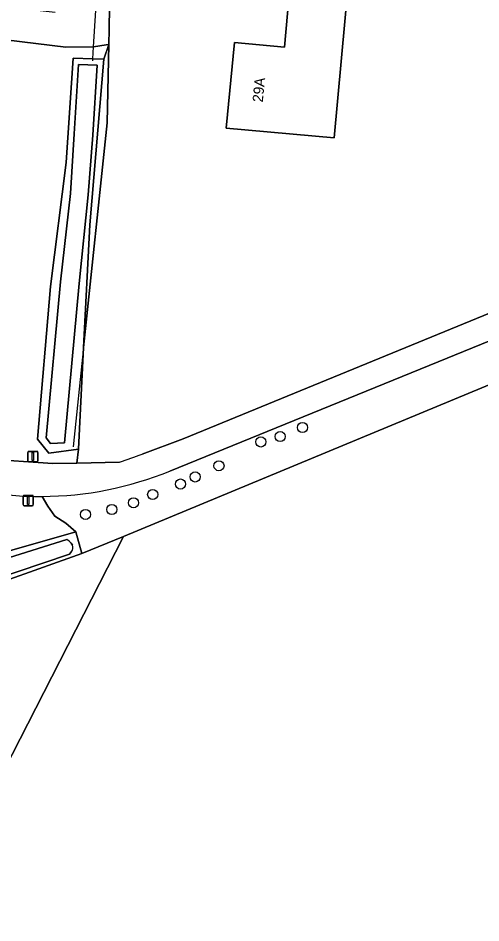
# Model space of a CAD drawing. Extents: x 162510 to 163918, y 388494 to 389774.
# Drawn here: x 162663.6 to 162708.2, y 389474.6 to 389562 of the extents above; entities that cross this region are included whole.
import ezdxf

# ---------------------------------------------------------------- set-up
doc = ezdxf.new("R2010")
doc.units = 0
for name, color, linetype in [('IMGEO_Afsluitpaal', 7, 'Continuous'), ('IMGEO_Boom', 7, 'Continuous'), ('IMGEO_Duiker', 7, 'Continuous'), ('IMGEO_Erf', 7, 'Continuous'), ('IMGEO_Grasland_agrarisch', 7, 'Continuous'), ('IMGEO_Grasland_overig', 7, 'Continuous'), ('IMGEO_Groenvoorziening', 7, 'Continuous'), ('IMGEO_Hek', 7, 'Continuous'), ('IMGEO_Loofbos', 7, 'Continuous'), ('IMGEO_Oever', 7, 'Continuous'), ('IMGEO_Pand', 7, 'Continuous'), ('IMGEO_Pand_nummerreeks', 7, 'Continuous'), ('IMGEO_Rijbaan_lokaal_onverhard', 7, 'Continuous'), ('IMGEO_Rijbaan_lokaal_open', 7, 'Continuous'), ('IMGEO_Waterloop', 7, 'Continuous')]:
    doc.layers.add(name, color=color, linetype=linetype)

msp = doc.modelspace()

# ---------------------------------------------------------------- linework, layer by layer
at = {"layer": 'IMGEO_Afsluitpaal'}
for p, q in [((162664.499, 389519.217), (162664.499, 389520.017)), ((162664.499, 389520.017), (162664.499, 389519.217)), ((162664.599, 389520.117), (162665.389, 389520.117)), ((162665.389, 389520.117), (162664.599, 389520.117)), ((162665.489, 389520.017), (162665.489, 389519.217)), ((162665.489, 389519.217), (162665.489, 389520.017)), ((162665.389, 389519.117), (162664.599, 389519.117)), ((162664.599, 389519.117), (162665.389, 389519.117)), ((162664.047, 389514.97), (162664.047, 389515.77)), ((162664.047, 389515.77), (162664.047, 389514.97)), ((162664.147, 389515.87), (162664.937, 389515.87)), ((162664.937, 389515.87), (162664.147, 389515.87)), ((162665.037, 389515.77), (162665.037, 389514.97)), ((162665.037, 389514.97), (162665.037, 389515.77)), ((162664.937, 389514.87), (162664.147, 389514.87)), ((162664.147, 389514.87), (162664.937, 389514.87))]:
    msp.add_line(p, q, dxfattribs=at)
for points in [[(162664.919, 389519.992), (162665.069, 389519.992), (162665.069, 389519.242), (162664.919, 389519.242), (162664.919, 389519.992)], [(162664.467, 389515.745), (162664.617, 389515.745), (162664.617, 389514.995), (162664.467, 389514.995), (162664.467, 389515.745)]]:
    msp.add_lwpolyline(points, dxfattribs=at)
for centre, start, end in [((162664.599, 389520.017), 90, 180), ((162664.599, 389520.017), 90, 180), ((162665.389, 389520.017), 0, 90), ((162665.389, 389520.017), 360, 90), ((162664.599, 389519.217), 180, 270), ((162664.599, 389519.217), 180, 270), ((162665.389, 389519.217), 270, 0), ((162665.389, 389519.217), 270, 0), ((162664.147, 389515.77), 90, 180), ((162664.147, 389515.77), 90, 180), ((162664.937, 389515.77), 0, 90), ((162664.937, 389515.77), 360, 90), ((162664.147, 389514.97), 180, 270), ((162664.147, 389514.97), 180, 270), ((162664.937, 389514.97), 270, 0), ((162664.937, 389514.97), 270, 0)]:
    msp.add_arc(centre, 0.1, start, end, dxfattribs=at)
at = {"layer": 'IMGEO_Boom'}
for centre in [(162691.022, 389522.421), (162688.864, 389521.544), (162686.995, 389521.025), (162682.955, 389518.729), (162680.661, 389517.646), (162679.239, 389516.963), (162676.559, 389515.948), (162674.703, 389515.155), (162672.623, 389514.495), (162670.069, 389514.029)]:
    msp.add_circle(centre, 0.489, dxfattribs=at)
at = {"layer": 'IMGEO_Duiker'}
msp.add_lwpolyline([(162670.773, 389557.836), (162670.785, 389558.031), (162670.855, 389559.19), (162671.066, 389562.679), (162671.154, 389564.123), (162671.18, 389564.555)], dxfattribs=at)
at = {"layer": 'IMGEO_Erf'}
for points in [[(162705.553, 389603.519), (162699.993, 389600.99), (162689.359, 389596.706), (162682.449, 389594.589), (162674.426, 389591.992), (162672.343, 389591.571), (162672.542, 389590.328), (162672.733, 389578.637), (162672.968, 389564.254), (162672.43, 389564.215), (162672.405, 389563.043), (162672.36, 389560.903), (162672.329, 389559.407), (162672.17, 389551.859), (162669.89, 389530.138), (162669.389, 389520.319), (162669.237, 389518.99), (162673.37, 389519.086)], [(162675.536, 389519.846), (162679.516, 389521.342), (162765.327, 389556.557), (162788.119, 389565.57), (162797.51, 389568.666), (162797.54, 389568.676)]]:
    msp.add_lwpolyline(points, dxfattribs=at)
msp.add_lwpolyline([(162694.093, 389550.388), (162683.643, 389551.344), (162684.466, 389559.606), (162689.277, 389559.141), (162689.907, 389566.028), (162695.476, 389565.519)], close=True, dxfattribs=at)
msp.add_arc((162664.749, 389547.121), 29.331, 287.09222, 291.5774, dxfattribs=at)
at = {"layer": 'IMGEO_Grasland_agrarisch'}
msp.add_lwpolyline([(162827.332, 389516.707), (162785.51, 389500), (162768.198, 389493.084), (162765.022, 389491.815), (162747.635, 389542.568), (162673.743, 389511.906), (162660.641, 389486.295), (162645.792, 389460.138), (162630.336, 389430.938), (162620.125, 389411.441), (162611.16, 389387.648), (162603.73, 389364.734), (162600.094, 389349.342), (162595.223, 389323.119), (162589.654, 389295.27), (162587.18, 389279.327)], dxfattribs=at)
at = {"layer": 'IMGEO_Grasland_overig'}
msp.add_lwpolyline([(162671.835, 389558.007), (162670.495, 389542.008), (162669.89, 389530.138), (162672.17, 389551.859), (162672.329, 389559.407)], close=True, dxfattribs=at)
msp.add_lwpolyline([(162620.125, 389411.441), (162630.336, 389430.938), (162645.792, 389460.138), (162660.641, 389486.295), (162673.743, 389511.906), (162669.724, 389510.239), (162658.13, 389506.139), (162654.637, 389500), (162643.958, 389481.233), (162638.44, 389471.713), (162635.685, 389466.725), (162634.256, 389464.148), (162613.419, 389423.521), (162610.195, 389417.846), (162606.388, 389409.531), (162602.54, 389399.816), (162600.275, 389394.519)], dxfattribs=at)
at = {"layer": 'IMGEO_Groenvoorziening'}
msp.add_lwpolyline([(162668.207, 389548.027), (162668.877, 389558.074), (162670.785, 389558.031), (162671.835, 389558.007), (162672.329, 389559.407), (162672.082, 389559.371), (162670.855, 389559.19), (162668.162, 389559.157), (162662.376, 389559.853), (162661.677, 389555.433), (162659.449, 389542.704), (162657.818, 389535.123), (162655.773, 389526.565), (162654.035, 389520.655), (162659.439, 389519.57), (162660.287, 389519.4), (162666.922, 389518.936), (162669.237, 389518.99), (162669.389, 389520.319), (162666.547, 389519.929), (162665.429, 389521.303), (162666.698, 389536.028)], close=True, dxfattribs=at)
msp.add_lwpolyline([(162659.366, 389513.063), (162659.445, 389512.758), (162659.494, 389512.434), (162659.314, 389509.549), (162669.129, 389512.345), (162668.181, 389513.167), (162667.108, 389513.867), (162666.432, 389514.835), (162665.882, 389515.761)], dxfattribs=at)
msp.add_arc((162665.71, 389549.239), 33.478, 260.35279, 270.29381, dxfattribs=at)
at = {"layer": 'IMGEO_Hek'}
for points in [[(162672.36, 389560.903), (162672.405, 389563.043)], [(162672.36, 389560.903), (162672.329, 389559.407)], [(162672.329, 389559.407), (162672.17, 389551.859), (162669.89, 389530.138)], [(162669.89, 389530.138), (162668.882, 389520.541)]]:
    msp.add_lwpolyline(points, dxfattribs=at)
at = {"layer": 'IMGEO_Loofbos'}
for points in [[(162750.859, 389543.906), (162749.683, 389547.352), (162678.223, 389518.21)], [(162665.882, 389515.761), (162666.432, 389514.835), (162667.108, 389513.867), (162668.181, 389513.167), (162669.129, 389512.345), (162669.724, 389510.239), (162673.743, 389511.906), (162747.635, 389542.568), (162750.859, 389543.906)]]:
    msp.add_lwpolyline(points, dxfattribs=at)
msp.add_arc((162665.691, 389549.044), 33.283, 270.32919, 292.1192, dxfattribs=at)
at = {"layer": 'IMGEO_Oever'}
for points in [[(162670.495, 389542.008), (162671.835, 389558.007), (162670.785, 389558.031), (162668.877, 389558.074), (162668.207, 389548.027), (162666.698, 389536.028), (162665.429, 389521.303), (162666.547, 389519.929), (162669.389, 389520.319), (162669.89, 389530.138)], [(162669.388, 389557.49), (162671.197, 389557.429), (162670.797, 389550.668), (162670.346, 389544.879), (162669.466, 389536.319), (162668.061, 389520.93), (162666.696, 389520.865), (162666.293, 389521.425), (162667.666, 389536.503), (162668.627, 389545.028), (162668.991, 389550.778)]]:
    msp.add_lwpolyline(points, close=True, dxfattribs=at)
for points in [[(162634.256, 389464.148), (162635.685, 389466.725), (162638.44, 389471.713), (162643.958, 389481.233), (162654.637, 389500), (162658.13, 389506.139), (162669.724, 389510.239), (162669.129, 389512.345), (162659.314, 389509.549), (162659.494, 389512.434), (162659.445, 389512.758), (162659.366, 389513.063)], [(162636.578, 389471.099), (162639.037, 389475.684), (162641.975, 389481.475), (162643.39, 389484.648), (162649.254, 389497.836), (162653.92, 389506.356), (162657.551, 389513.059), (162658.86, 389512.638), (162658.709, 389508.6), (162668.26, 389511.601)], [(162668.704, 389511.263), (162668.826, 389511.049)], [(162668.737, 389510.454), (162668.635, 389510.321), (162668.523, 389510.19), (162658.39, 389506.787), (162657.559, 389506.341), (162643.33, 389480.856), (162640.007, 389475.184), (162633.793, 389463.772), (162631.706, 389459.707), (162629.667, 389455.808), (162626.032, 389448.621), (162622.316, 389441.292), (162613.522, 389424.144), (162610.047, 389417.95), (162607.536, 389412.566), (162604.252, 389404.959), (162602.241, 389399.806), (162600.325, 389394.951), (162599.784, 389393.765), (162599.088, 389391.643), (162596.849, 389385.147), (162595.479, 389380.912), (162593.289, 389373.253), (162591.117, 389365.304)]]:
    msp.add_lwpolyline(points, dxfattribs=at)
for centre, radius, start, end in [((162667.625, 389510.306), 1.442, 41.56592, 63.87285), ((162668.281, 389510.826), 0.589, 320.78844, 22.19712)]:
    msp.add_arc(centre, radius, start, end, dxfattribs=at)
at = {"layer": 'IMGEO_Pand'}
msp.add_lwpolyline([(162689.277, 389559.141), (162684.466, 389559.606), (162683.643, 389551.344), (162694.093, 389550.388), (162695.476, 389565.519), (162689.907, 389566.028)], close=True, dxfattribs=at)
at = {"layer": 'IMGEO_Rijbaan_lokaal_onverhard'}
for points in [[(162749.683, 389547.352), (162758.463, 389550.933), (162759.862, 389551.503), (162762.697, 389552.483), (162768.515, 389554.179), (162781.928, 389559.733), (162790.446, 389561.446), (162794.384, 389561.504), (162797.303, 389560.83), (162798.23, 389560.184), (162799.836, 389559.064), (162802.983, 389552.671), (162805.096, 389552.992), (162802.739, 389560.703), (162802.079, 389561.714), (162802.196, 389565.731), (162800.822, 389569.758), (162797.54, 389568.676), (162797.51, 389568.666), (162788.119, 389565.57), (162765.327, 389556.557), (162679.516, 389521.342), (162675.536, 389519.846)], [(162678.223, 389518.21), (162749.683, 389547.352)], [(162673.37, 389519.086), (162669.237, 389518.99), (162666.922, 389518.936), (162660.287, 389519.4), (162659.439, 389519.57), (162654.035, 389520.655), (162653.086, 389517.429), (162660.1, 389516.234)]]:
    msp.add_lwpolyline(points, dxfattribs=at)
for centre, radius, start, end in [((162664.749, 389547.121), 29.331, 287.09222, 291.5774), ((162665.691, 389549.044), 33.283, 270.32919, 292.1192), ((162665.71, 389549.239), 33.478, 260.35279, 270.29381)]:
    msp.add_arc(centre, radius, start, end, dxfattribs=at)
at = {"layer": 'IMGEO_Rijbaan_lokaal_open'}
msp.add_lwpolyline([(162667.146, 389562.495), (162662.78, 389562.997), (162662.376, 389559.853), (162668.162, 389559.157), (162670.855, 389559.19), (162672.082, 389559.371), (162672.329, 389559.407), (162672.36, 389560.903), (162672.405, 389563.043)], dxfattribs=at)
at = {"layer": 'IMGEO_Waterloop'}
msp.add_lwpolyline([(162671.197, 389557.429), (162669.388, 389557.49), (162668.991, 389550.778), (162668.627, 389545.028), (162667.666, 389536.503), (162666.293, 389521.425), (162666.696, 389520.865), (162668.061, 389520.93), (162669.466, 389536.319), (162670.346, 389544.879), (162670.797, 389550.668)], close=True, dxfattribs=at)
for points in [[(162668.26, 389511.601), (162658.709, 389508.6), (162658.86, 389512.638), (162657.551, 389513.059), (162653.92, 389506.356), (162649.254, 389497.836), (162643.39, 389484.648), (162641.975, 389481.475), (162639.037, 389475.684), (162636.578, 389471.099)], [(162668.826, 389511.049), (162668.704, 389511.263)], [(162668.523, 389510.19), (162668.635, 389510.321), (162668.737, 389510.454)], [(162591.117, 389365.304), (162593.289, 389373.253), (162595.479, 389380.912), (162596.849, 389385.147), (162599.088, 389391.643), (162599.784, 389393.765), (162600.325, 389394.951), (162602.241, 389399.806), (162604.252, 389404.959), (162607.536, 389412.566), (162610.047, 389417.95), (162613.522, 389424.144), (162622.316, 389441.292), (162626.032, 389448.621), (162629.667, 389455.808), (162631.706, 389459.707), (162633.793, 389463.772), (162640.007, 389475.184), (162643.33, 389480.856), (162657.559, 389506.341), (162658.39, 389506.787), (162668.523, 389510.19)]]:
    msp.add_lwpolyline(points, dxfattribs=at)
for centre, radius, start, end in [((162667.625, 389510.306), 1.442, 41.56592, 63.87285), ((162668.281, 389510.826), 0.589, 320.78844, 22.19712)]:
    msp.add_arc(centre, radius, start, end, dxfattribs=at)

# ---------------------------------------------------------------- texts
at = {"layer": 'IMGEO_Pand_nummerreeks'}
msp.add_text('29A', height=1, rotation=84.31138, dxfattribs=at).set_placement((162687.183, 389553.8))

doc.saveas('drawing.dxf')
